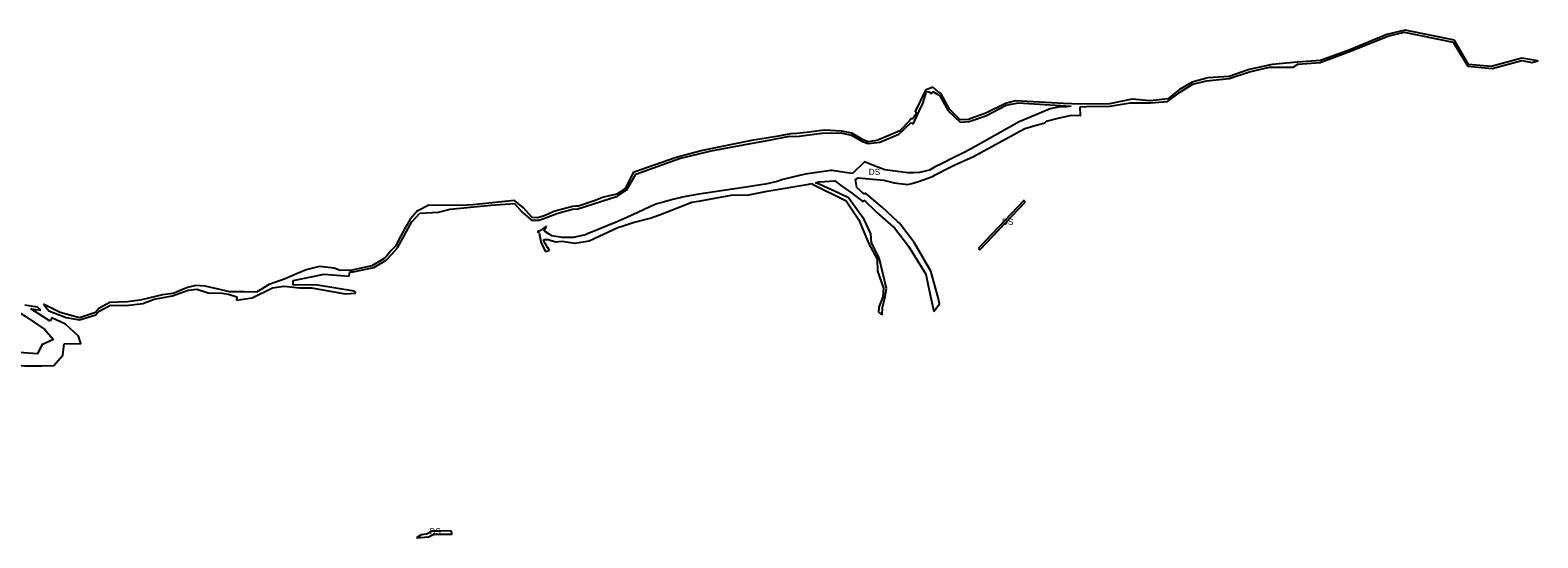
# Model space of a CAD drawing. Extents: x -477304 to -465641, y -1159113 to -1149285.
# Drawn here: x -468631 to -466441, y -1156788 to -1156051 of the extents above; entities that cross this region are included whole.
import ezdxf

# ---------------------------------------------------------------- set-up
doc = ezdxf.new("R2010")
doc.units = 0
doc.layers.add('35', color=7, linetype='Continuous')

msp = doc.modelspace()

# ---------------------------------------------------------------- linework, layer by layer
at = {"layer": '35'}
for p, q in [((-466713.6, -1156081.9), (-466659.6, -1156059.8)), ((-466634.4, -1156051.2), (-466660.7, -1156057.5)), ((-466562.3, -1156065.6), (-466634.4, -1156051.2)), ((-466542.2, -1156100.9), (-466562.3, -1156065.6)), ((-466791.2, -1156097.6), (-466827.5, -1156101.1)), ((-466543.3, -1156103.6), (-466507.8, -1156106.7)), ((-466920.7, -1156120.3), (-466943.7, -1156126.8)), ((-466942.5, -1156129.4), (-466922.8, -1156124.5)), ((-466922.8, -1156124.5), (-466889.8, -1156121.2)), ((-466889.7, -1156118.3), (-466920.7, -1156120.3)), ((-466889.8, -1156121.2), (-466860.3, -1156111.5)), ((-466860.3, -1156111.5), (-466831.1, -1156105.1)), ((-467320.1, -1156133.9), (-467331, -1156138.3)), ((-467311.3, -1156141.5), (-467320.1, -1156133.9)), ((-467309.9, -1156146.4), (-467298, -1156168.4)), ((-466979.6, -1156154.9), (-466960.7, -1156140.6)), ((-466962.1, -1156137.5), (-466978.8, -1156150.9)), ((-466943.7, -1156126.8), (-466962.1, -1156137.5)), ((-466960.7, -1156140.6), (-466942.5, -1156129.4)), ((-467348.6, -1156187.6), (-467340, -1156168.9)), ((-467340, -1156168.9), (-467334.8, -1156157.8)), ((-467280.6, -1156181.3), (-467295.8, -1156165.9)), ((-467196.3, -1156156.9), (-467119.3, -1156161.3)), ((-467128.2, -1156163.1), (-467135.3, -1156162.7)), ((-467119.3, -1156161.3), (-467128.2, -1156163.1)), ((-467063.8, -1156158), (-467106.2, -1156158.6)), ((-467106.1, -1156162.4), (-467087.2, -1156161.5)), ((-467087.2, -1156161.5), (-467065.9, -1156162)), ((-467065.9, -1156162), (-467033.4, -1156156.9)), ((-467030.6, -1156151.6), (-467063.8, -1156158)), ((-467004.3, -1156153.8), (-467030.6, -1156151.6)), ((-466978.8, -1156150.9), (-467004.3, -1156153.8)), ((-467369.5, -1156202), (-467351.5, -1156185.2)), ((-467353.9, -1156182.8), (-467368, -1156197.1)), ((-467351.6, -1156179.4), (-467353.9, -1156182.8)), ((-467349.8, -1156180.6), (-467351.6, -1156179.4)), ((-467351.5, -1156185.2), (-467348.6, -1156187.6)), ((-467343.2, -1156171.4), (-467349.8, -1156180.6)), ((-467344.9, -1156170.2), (-467343.2, -1156171.4)), ((-467186.8, -1156194), (-467169.9, -1156189.1)), ((-467582.2, -1156215.3), (-467558, -1156210.8)), ((-467558, -1156210.8), (-467528.4, -1156205.3)), ((-467528.4, -1156205.3), (-467518.1, -1156205.6)), ((-467517.5, -1156201.1), (-467527, -1156201.9)), ((-467518.1, -1156205.6), (-467481.2, -1156200.6)), ((-467503.9, -1156199.8), (-467517.5, -1156201.1)), ((-467478, -1156196.6), (-467503.9, -1156199.8)), ((-467481.2, -1156200.6), (-467453.8, -1156200.4)), ((-467452.3, -1156197.8), (-467478, -1156196.6)), ((-467453.8, -1156200.4), (-467438.3, -1156203.6)), ((-467438.3, -1156203.6), (-467422.5, -1156213)), ((-467240.6, -1156223.4), (-467186.8, -1156194)), ((-467289.1, -1156247.1), (-467261.2, -1156234.5)), ((-467265.5, -1156223.8), (-467268.6, -1156225.6)), ((-467261.2, -1156234.5), (-467240.6, -1156223.4)), ((-467692.9, -1156236.1), (-467755.4, -1156257.9)), ((-467304.8, -1156243.8), (-467317.7, -1156250.3)), ((-467292.7, -1156237.7), (-467304.8, -1156243.8)), ((-467755.4, -1156257.9), (-467767, -1156281.8)), ((-467569.8, -1156275.9), (-467591.3, -1156279.1)), ((-467560.6, -1156284.8), (-467500.3, -1156274.8)), ((-467500.3, -1156274.8), (-467496.5, -1156273.9)), ((-467496.5, -1156273.9), (-467493.9, -1156275.2)), ((-467485.4, -1156274.9), (-467490.8, -1156272.7)), ((-467456.9, -1156287.9), (-467485.4, -1156274.9)), ((-467428.4, -1156265.6), (-467391.2, -1156269)), ((-467391.2, -1156269), (-467376.3, -1156273)), ((-467350.9, -1156258.4), (-467356.6, -1156258.4)), ((-467914.9, -1156309.2), (-467927.6, -1156298.3)), ((-467835.6, -1156310.4), (-467778.1, -1156292.3)), ((-467798.5, -1156293.5), (-467810.8, -1156298.6)), ((-467779.1, -1156289.1), (-467798.5, -1156293.5)), ((-467767, -1156281.8), (-467779.1, -1156289.1)), ((-467778.1, -1156292.3), (-467765.2, -1156283.3)), ((-467697.7, -1156297.2), (-467715.2, -1156301.8)), ((-467692, -1156295.6), (-467697.7, -1156297.2)), ((-467687.3, -1156294.4), (-467692, -1156295.6)), ((-467684.3, -1156293.9), (-467687.3, -1156294.4)), ((-467659.8, -1156289.1), (-467684.3, -1156293.9)), ((-467670.3, -1156301), (-467657.6, -1156299.2)), ((-467611.3, -1156282), (-467659.8, -1156289.1)), ((-467657.6, -1156299.2), (-467618.3, -1156291.5)), ((-467618.3, -1156291.5), (-467613.3, -1156290.9)), ((-467591.3, -1156279.1), (-467611.3, -1156282)), ((-467419.6, -1156290), (-467430.8, -1156279.8)), ((-467421.5, -1156300.6), (-467420.4, -1156298)), ((-467187.6, -1156298.1), (-467253.7, -1156367.7)), ((-467252.1, -1156370), (-467185.9, -1156300.8)), ((-467185.9, -1156300.8), (-467187.6, -1156298.1)), ((-468052.2, -1156305.2), (-468069.2, -1156314)), ((-468005.7, -1156305.7), (-468052.2, -1156305.2)), ((-468021.1, -1156311.3), (-467962.3, -1156305.2)), ((-467988.1, -1156304.7), (-468005.7, -1156305.7)), ((-467962.3, -1156305.2), (-467927.7, -1156302.9)), ((-467902.3, -1156323.3), (-467914.9, -1156309.2)), ((-467843.4, -1156307.4), (-467870.7, -1156314.7)), ((-467843.5, -1156310.9), (-467835.6, -1156310.4)), ((-467839.1, -1156306.9), (-467843.4, -1156307.4)), ((-467749.7, -1156316.2), (-467777.5, -1156328.8)), ((-467731, -1156307.8), (-467749.7, -1156316.2)), ((-467721.2, -1156303.4), (-467731, -1156307.8)), ((-467730.7, -1156324.3), (-467715.7, -1156318.6)), ((-467715.2, -1156301.8), (-467721.2, -1156303.4)), ((-467715.7, -1156318.6), (-467670.3, -1156301)), ((-467405.7, -1156311.7), (-467400.9, -1156316.4)), ((-467400.9, -1156316.4), (-467378, -1156336.5)), ((-468083.9, -1156334.1), (-468087.3, -1156340)), ((-467903.1, -1156326.9), (-467891.7, -1156326.9)), ((-467894, -1156323.6), (-467902.3, -1156323.3)), ((-467890.9, -1156342.4), (-467894.8, -1156343.7)), ((-467894.8, -1156343.7), (-467891.9, -1156345.7)), ((-467881.5, -1156335.7), (-467890.9, -1156342.4)), ((-467884.5, -1156342.9), (-467881.5, -1156335.7)), ((-467882.6, -1156344.2), (-467884.5, -1156342.9)), ((-467873.5, -1156349.9), (-467882.6, -1156344.2)), ((-467819.3, -1156357.3), (-467776.5, -1156337.4)), ((-467776.5, -1156337.4), (-467772.7, -1156336.1)), ((-467891.9, -1156345.7), (-467889.1, -1156360.3)), ((-467889.1, -1156360.3), (-467882.6, -1156372.4)), ((-467885.7, -1156355.2), (-467878.7, -1156355.1)), ((-467878.7, -1156355.1), (-467868.2, -1156358.6)), ((-467868.2, -1156358.6), (-467858.6, -1156357.5)), ((-467858.6, -1156357.5), (-467840.3, -1156360.4)), ((-467840.3, -1156360.4), (-467819.3, -1156357.3)), ((-467413.3, -1156361.3), (-467400.9, -1156383.7)), ((-467356.8, -1156363), (-467355.5, -1156364.7)), ((-468114.2, -1156384.9), (-468105.9, -1156376.5)), ((-468107.4, -1156371.6), (-468113.4, -1156379)), ((-468105.9, -1156376.5), (-468097.5, -1156367.3)), ((-467882.6, -1156372.4), (-467876.7, -1156371.3)), ((-467253.7, -1156367.7), (-467252.1, -1156370)), ((-468245.3, -1156405.6), (-468260.8, -1156412.1)), ((-468249.4, -1156414.9), (-468204.4, -1156405.5)), ((-468189.9, -1156396.8), (-468210.9, -1156394.2)), ((-468204.4, -1156405.5), (-468167.8, -1156408.2)), ((-468167.8, -1156408.2), (-468166.9, -1156402.1)), ((-468166.9, -1156402.1), (-468162, -1156401.9)), ((-468413.7, -1156433.1), (-468401.6, -1156428.5)), ((-468401.6, -1156428.5), (-468389.2, -1156427.2)), ((-468389.2, -1156427.2), (-468372.5, -1156432.7)), ((-468284.1, -1156420.5), (-468302.6, -1156431.5)), ((-468260.8, -1156412.1), (-468284.1, -1156420.5)), ((-468158, -1156433.2), (-468160.4, -1156430.2)), ((-468620.6, -1156453.4), (-468638.8, -1156450.7)), ((-468615.9, -1156457.6), (-468620.6, -1156453.4)), ((-468531, -1156459.3), (-468514.6, -1156450.3)), ((-468514.6, -1156450.3), (-468491.9, -1156451)), ((-468491.9, -1156451), (-468467.7, -1156447.9)), ((-468472.1, -1156443.2), (-468490, -1156445.8)), ((-468467.7, -1156447.9), (-468451.3, -1156442)), ((-468451.3, -1156442), (-468424.3, -1156436.8)), ((-468424.3, -1156436.8), (-468413.7, -1156433.1)), ((-468372.5, -1156432.7), (-468352.2, -1156433.1)), ((-468352.2, -1156433.1), (-468343.3, -1156434.5)), ((-468343.3, -1156434.5), (-468331.1, -1156438.3)), ((-468331.1, -1156438.3), (-468331.7, -1156443.2)), ((-467398.4, -1156453.2), (-467399.3, -1156460.5)), ((-467393.7, -1156464.5), (-467393.4, -1156454)), ((-468602.3, -1156473.6), (-468630, -1156456)), ((-468630, -1156456), (-468615.9, -1156457.6)), ((-468536.1, -1156461.1), (-468559.5, -1156468.7)), ((-468559.4, -1156471.8), (-468536, -1156464.6)), ((-468531.6, -1156455.4), (-468536.1, -1156461.1)), ((-468536, -1156464.6), (-468531, -1156459.3)), ((-467399.3, -1156460.5), (-467393.7, -1156464.5)), ((-468609.9, -1156485.8), (-468607.9, -1156488)), ((-468607.9, -1156488), (-468597.3, -1156500.2)), ((-468020.9, -1156778.3), (-468034.7, -1156778.6)), ((-468018.7, -1156780.8), (-468020.9, -1156778.3)), ((-468063.2, -1156783.8), (-468070.1, -1156788.3)), ((-468070.1, -1156788.3), (-468052.7, -1156787.1)), ((-468055.7, -1156783.1), (-468063.2, -1156783.8))]:
    msp.add_line(p, q, dxfattribs=at)
for points in [[(-466660.7, -1156057.5), (-466714.5, -1156079.6), (-466757, -1156095.2), (-466791.2, -1156097.6)], [(-466659.6, -1156059.8), (-466635.4, -1156054.3), (-466564.7, -1156068.5), (-466543.3, -1156103.6)], [(-466827.5, -1156101.1), (-466860.6, -1156108.4), (-466889.7, -1156118.3)], [(-466831.1, -1156105.1), (-466797, -1156104.7), (-466790, -1156100.6), (-466757.6, -1156098.3), (-466713.6, -1156081.9)], [(-466450, -1156098.3), (-466441.5, -1156095.9), (-466464.8, -1156091.7), (-466509.5, -1156103.7), (-466542.2, -1156100.9)], [(-466507.8, -1156106.7), (-466464.9, -1156095), (-466450, -1156098.3)], [(-467331, -1156138.3), (-467345.8, -1156169.5), (-467344.9, -1156170.2)], [(-467334.8, -1156157.8), (-467329.3, -1156140.3), (-467325.8, -1156140.6)], [(-467325.8, -1156140.6), (-467322, -1156143), (-467320.3, -1156140.1)], [(-467320.3, -1156140.1), (-467312.8, -1156144.6), (-467309.9, -1156146.4)], [(-467295.8, -1156165.9), (-467307.9, -1156143.8), (-467311.3, -1156141.5)], [(-467298, -1156168.4), (-467280.7, -1156184.8), (-467267.6, -1156184)], [(-467267.6, -1156184), (-467243.3, -1156175.4), (-467213.7, -1156160), (-467196.3, -1156156.9)], [(-467135.3, -1156162.7), (-467149.9, -1156165.2), (-467165.8, -1156172.1), (-467194.8, -1156184.4), (-467265.5, -1156223.8)], [(-467214.8, -1156157.8), (-467243.1, -1156171.9), (-467259.5, -1156177.7)], [(-467106.2, -1156158.6), (-467130.2, -1156157.7), (-467200.1, -1156154), (-467214.8, -1156157.8)], [(-467118.9, -1156174.6), (-467105.5, -1156175), (-467106.1, -1156162.4)], [(-467033.4, -1156156.9), (-467004.1, -1156156.9), (-466979.6, -1156154.9)], [(-467259.5, -1156177.7), (-467268.2, -1156181), (-467280.6, -1156181.3)], [(-467169.9, -1156189.1), (-467157.6, -1156185.5), (-467155.1, -1156183.4)], [(-467155.1, -1156183.4), (-467138.3, -1156178.8), (-467118.9, -1156174.6)], [(-467583.5, -1156211.5), (-467654.5, -1156226), (-467692.9, -1156236.1)], [(-467527, -1156201.9), (-467547.4, -1156205.6), (-467583.5, -1156211.5)], [(-467422.1, -1156209.9), (-467437.7, -1156200.9), (-467452.3, -1156197.8)], [(-467422.5, -1156213), (-467414.2, -1156215.9), (-467397, -1156213.7), (-467369.5, -1156202)], [(-467404.3, -1156211.7), (-467414.2, -1156213.1), (-467422.1, -1156209.9)], [(-467368, -1156197.1), (-467400.3, -1156211), (-467404.3, -1156211.7)], [(-467688.3, -1156237.6), (-467642.2, -1156226.6), (-467582.2, -1156215.3)], [(-467268.6, -1156225.6), (-467273.9, -1156228.1), (-467292.7, -1156237.7)], [(-467765.2, -1156283.3), (-467751.5, -1156260.3), (-467688.3, -1156237.6)], [(-467468.2, -1156255), (-467505.6, -1156260.5), (-467515.6, -1156262.9)], [(-467436.8, -1156259.4), (-467448.1, -1156257.7), (-467466.5, -1156254.8), (-467468.2, -1156255)], [(-467404.1, -1156248.5), (-467419.6, -1156242.5), (-467436.8, -1156259.4)], [(-467356.6, -1156258.4), (-467389.9, -1156254.1), (-467404.1, -1156248.5)], [(-467317.7, -1156250.3), (-467325.1, -1156254.6), (-467339.4, -1156258)], [(-467316.6, -1156261.4), (-467294.9, -1156250.1), (-467289.1, -1156247.1)], [(-467546.2, -1156270.7), (-467563.1, -1156274.9), (-467569.8, -1156275.9)], [(-467515.6, -1156262.9), (-467538, -1156268.2), (-467546.2, -1156270.7)], [(-467493.9, -1156275.2), (-467446.2, -1156299.2), (-467427.5, -1156326.5), (-467413.3, -1156361.3)], [(-467490.8, -1156272.7), (-467486.3, -1156271.6), (-467485.5, -1156271.6)], [(-467485.5, -1156271.6), (-467462.7, -1156270), (-467460.4, -1156271.6), (-467454.1, -1156276), (-467438.1, -1156287.4), (-467421.5, -1156300.6)], [(-467430.8, -1156279.8), (-467432.4, -1156268.1), (-467428.4, -1156265.6)], [(-467376.3, -1156273), (-467356.7, -1156275.5), (-467350.8, -1156273.7)], [(-467339.4, -1156258), (-467348.2, -1156258.4), (-467350.9, -1156258.4)], [(-467350.8, -1156273.7), (-467341.1, -1156270.7), (-467320.7, -1156263.5), (-467316.6, -1156261.4)], [(-467927.6, -1156298.3), (-467983.2, -1156304.5), (-467988.1, -1156304.7)], [(-467810.8, -1156298.6), (-467834.9, -1156306.5), (-467839.1, -1156306.9)], [(-467613.3, -1156290.9), (-467587.3, -1156290.4), (-467560.6, -1156284.8)], [(-467410.3, -1156346.8), (-467420.1, -1156326.2), (-467442.8, -1156294.4), (-467456.9, -1156287.9)], [(-467420.4, -1156298), (-467417.4, -1156300.5), (-467405.7, -1156311.7)], [(-467393.9, -1156308.2), (-467417.9, -1156287.9), (-467419.6, -1156290)], [(-468097.5, -1156367.3), (-468076.8, -1156329.4), (-468065.4, -1156316.7)], [(-468069.2, -1156314), (-468079.1, -1156325.5), (-468083.9, -1156334.1)], [(-468065.4, -1156316.7), (-468038.2, -1156315.2), (-468021.1, -1156311.3)], [(-467927.7, -1156302.9), (-467916.8, -1156315.6), (-467903.1, -1156326.9)], [(-467870.7, -1156314.7), (-467883.3, -1156320.3), (-467894, -1156323.6)], [(-467891.7, -1156326.9), (-467881.1, -1156323), (-467866.5, -1156317.2), (-467843.5, -1156310.9)], [(-467368.7, -1156331.4), (-467371.5, -1156328.8), (-467393.9, -1156308.2)], [(-468087.3, -1156340), (-468095.6, -1156355.2), (-468100.2, -1156364.5), (-468107.4, -1156371.6)], [(-467777.5, -1156328.8), (-467821.9, -1156347), (-467824.8, -1156348.2)], [(-467772.7, -1156336.1), (-467755.5, -1156330.3), (-467730.7, -1156324.3)], [(-467378, -1156336.5), (-467375.8, -1156338.4), (-467356.8, -1156363)], [(-467323, -1156400.9), (-467347.2, -1156359.7), (-467368.7, -1156331.4)], [(-467876.7, -1156371.3), (-467884.1, -1156359.7), (-467885.7, -1156355.2)], [(-467824.8, -1156348.2), (-467842.7, -1156352.1), (-467858.6, -1156352.1), (-467873.5, -1156349.9)], [(-467387.7, -1156426.1), (-467398, -1156381.9), (-467409.2, -1156359.9), (-467410.3, -1156346.8)], [(-467355.5, -1156364.7), (-467330.4, -1156405.5), (-467326.8, -1156422.1)], [(-468113.4, -1156379), (-468117.1, -1156382.9), (-468135, -1156393.6), (-468164.2, -1156399.6), (-468181.1, -1156400), (-468189.9, -1156396.8)], [(-468162, -1156401.9), (-468132.2, -1156396), (-468114.2, -1156384.9)], [(-467400.9, -1156383.7), (-467400.7, -1156401), (-467391.7, -1156425.8), (-467392.7, -1156438.3), (-467398.4, -1156453.2)], [(-468210.9, -1156394.2), (-468230.4, -1156399), (-468245.3, -1156405.6)], [(-467318.5, -1156459.6), (-467310.7, -1156448.4), (-467312.6, -1156439.2), (-467323, -1156400.9)], [(-468402.9, -1156424.9), (-468423.4, -1156433.3), (-468439.2, -1156435.4)], [(-468341.2, -1156431.1), (-468376.8, -1156422.9), (-468390.7, -1156422), (-468402.9, -1156424.9)], [(-468302.6, -1156431.5), (-468320.6, -1156431.3), (-468341.2, -1156431.1)], [(-468331.7, -1156443.2), (-468308.6, -1156439.6), (-468279.3, -1156425.5)], [(-468279.3, -1156425.5), (-468262.1, -1156422.9), (-468240, -1156425.2), (-468222.6, -1156425.4)], [(-468160.4, -1156430.2), (-468213.7, -1156421.6), (-468249.1, -1156421.1), (-468249.4, -1156414.9)], [(-468222.6, -1156425.4), (-468173.9, -1156434), (-468158, -1156433.2)], [(-467393.4, -1156454), (-467389.7, -1156440.4), (-467387.7, -1156426.1)], [(-467326.8, -1156422.1), (-467321.4, -1156446.7), (-467318.5, -1156459.6)], [(-468665.3, -1156451.7), (-468651.2, -1156458.6), (-468638.3, -1156466.4), (-468609.9, -1156485.8)], [(-468559.5, -1156468.7), (-468587.6, -1156461), (-468611.9, -1156448.9)], [(-468611.9, -1156448.9), (-468604, -1156458.7), (-468578.9, -1156468.2), (-468559.4, -1156471.8)], [(-468490, -1156445.8), (-468515.4, -1156446.8), (-468531.6, -1156455.4)], [(-468439.2, -1156435.4), (-468469.7, -1156442.6), (-468472.1, -1156443.2)], [(-468579.9, -1156478), (-468599.6, -1156469.1), (-468602.3, -1156473.6)], [(-468581.6, -1156506.8), (-468557.5, -1156505.9), (-468560.8, -1156495.3), (-468579.9, -1156478)], [(-468597.3, -1156500.2), (-468614.1, -1156508), (-468620.5, -1156521.2), (-468674.9, -1156517.2)], [(-468614.4, -1156538.4), (-468596.8, -1156538.2), (-468583.7, -1156522.9), (-468581.6, -1156506.8)], [(-468670.7, -1156535.8), (-468639, -1156538.7), (-468614.4, -1156538.4)], [(-468034.7, -1156778.6), (-468047.2, -1156778.8), (-468055.7, -1156783.1)], [(-468024.7, -1156782.8), (-468019, -1156782.8), (-468018.7, -1156780.8)], [(-468052.7, -1156787.1), (-468044.6, -1156783.2), (-468024.7, -1156782.8)]]:
    msp.add_lwpolyline(points, dxfattribs=at)

# ---------------------------------------------------------------- texts
for p in [(-467413.3, -1156261.5), (-467219.8, -1156334), (-468051.5, -1156783.3)]:
    msp.add_text('DS', height=9, dxfattribs=at).set_placement(p)

doc.saveas('drawing.dxf')
